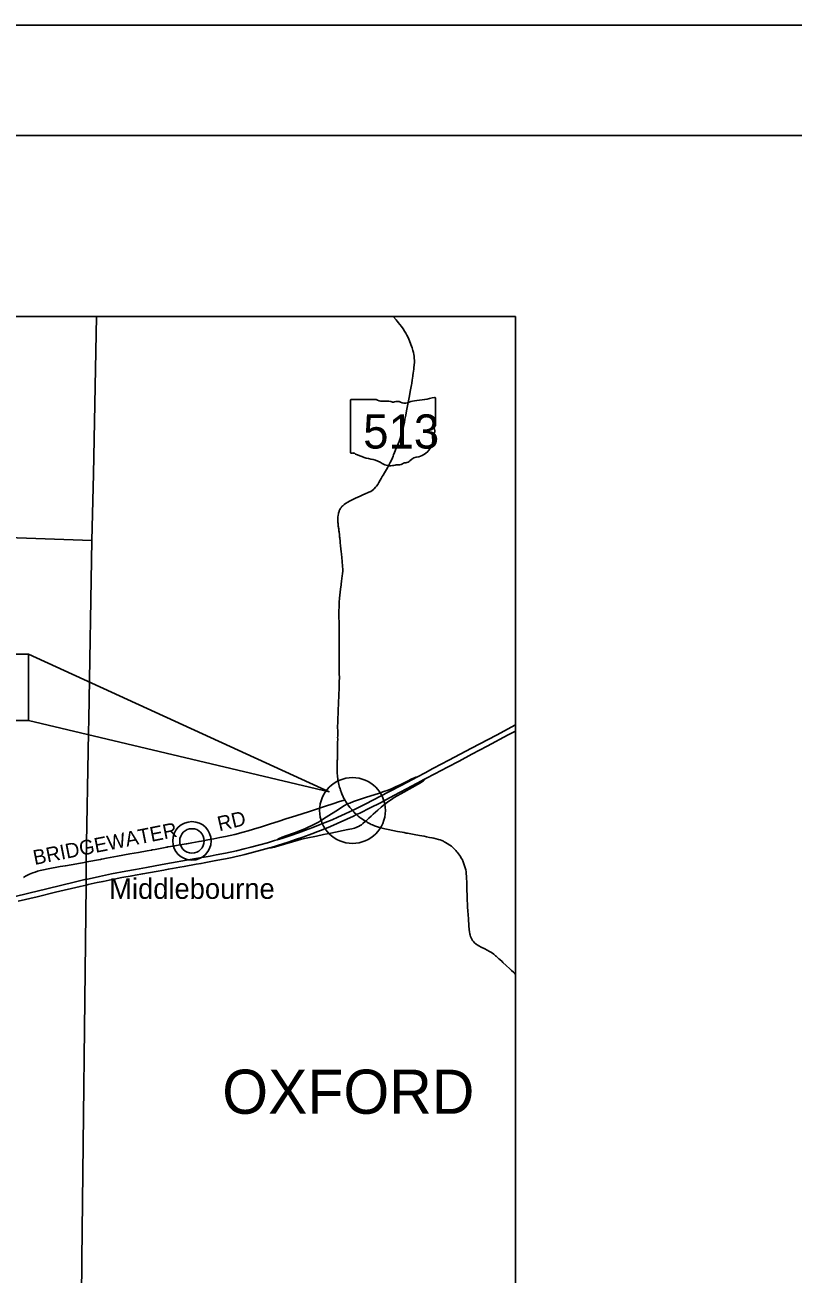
# Model space of a CAD drawing. Extents: x -29.6 to 34, y 0 to 22.
# Drawn here: x 18.65 to 22.13, y 16.34 to 22 of the extents above; entities that cross this region are included whole.
import ezdxf

# ---------------------------------------------------------------- set-up
doc = ezdxf.new("R2010")
doc.units = 0
for name, color, linetype in [('BR_P_Gen_Text', 7, 'Continuous'), ('Default', 7, 'Continuous'), ('GM_X_County_Road', 7, 'Continuous'), ('GM_X_County_Road_Text', 7, 'Continuous'), ('GM_X_Interchange_Ramps', 7, 'Continuous'), ('GM_X_Interstate_Route', 7, 'Continuous'), ('GM_X_State_Route', 7, 'Continuous'), ('GM_X_State_Shield', 7, 'Continuous'), ('GM_X_Township', 7, 'Continuous'), ('GM_X_Township_Text', 7, 'Continuous'), ('GM_X_Unincorporated', 7, 'Continuous'), ('GM_X_Unincorporated_Location', 7, 'Continuous'), ('GM_X_Unincorporated_Text', 7, 'Continuous'), ('GM_X_US_Route', 7, 'Continuous'), ('SH_Border', 7, 'Continuous'), ('SH_Cut_Line', 7, 'Continuous'), ('SH_Text', 7, 'Continuous')]:
    doc.layers.add(name, color=color, linetype=linetype)

msp = doc.modelspace()

# ---------------------------------------------------------------- linework, layer by layer
at = {"layer": 'BR_P_Gen_Text'}
for points in [[(17.1077, 19.1512), (18.6674, 19.1512), (18.6674, 18.8509), (17.1077, 18.8509)], [(18.6674, 19.1512), (18.6674, 18.8509), (20.0294, 18.5277)]]:
    msp.add_lwpolyline(points, close=True, dxfattribs=at)
at = {"layer": 'Default'}
msp.add_circle((20.1356, 18.443), 0.149, dxfattribs=at)
at = {"layer": 'GM_X_County_Road'}
for points in [[(19.4514, 18.305), (19.4797, 18.3101), (19.5073, 18.3153), (19.5343, 18.3205), (19.5606, 18.3257), (19.6029, 18.3352), (19.6396, 18.3445), (19.6628, 18.351), (19.6863, 18.358), (19.7227, 18.3694), (19.7591, 18.3811), (19.8034, 18.3953), (19.833, 18.4048), (19.8789, 18.4195), (19.9408, 18.4388), (19.9636, 18.4462), (20.0131, 18.4625), (20.0459, 18.4728), (20.0762, 18.4834), (20.0929, 18.4888), (20.1004, 18.4912)], [(19.2951, 18.2773), (19.2982, 18.2779), (19.3226, 18.2823), (19.3458, 18.2862), (19.3638, 18.2892), (19.3814, 18.2922), (19.3845, 18.2928)], [(19.3845, 18.2928), (19.3923, 18.2944), (19.4075, 18.2971), (19.4406, 18.3031), (19.4514, 18.305)], [(18.9931, 18.2217), (18.9987, 18.2227), (19.0004, 18.223), (19.0211, 18.2272), (19.0706, 18.2358), (19.1271, 18.2463), (19.1659, 18.2532), (19.2045, 18.2604), (19.2253, 18.2641), (19.2278, 18.2646)], [(19.2278, 18.2646), (19.2411, 18.2669), (19.2868, 18.2756), (19.294, 18.2771), (19.2951, 18.2773)], [(18.644, 18.1398), (18.6541, 18.1457), (18.6632, 18.1504), (18.6719, 18.1543), (18.6867, 18.1605), (18.6969, 18.1644), (18.7074, 18.1677), (18.7208, 18.1713), (18.7357, 18.1748), (18.7557, 18.1789), (18.8102, 18.1888), (18.8345, 18.1933), (18.9286, 18.2099)], [(18.9286, 18.2099), (18.932, 18.2105), (18.9931, 18.2217)]]:
    msp.add_lwpolyline(points, dxfattribs=at)
at = {"layer": 'GM_X_Interchange_Ramps'}
for points in [[(20.4268, 18.594), (20.4226, 18.5934), (20.4191, 18.5924), (20.4123, 18.59), (20.4051, 18.5864), (20.3842, 18.576), (20.351, 18.5594), (20.3312, 18.55), (20.3152, 18.543), (20.2969, 18.5359), (20.277, 18.5288), (20.2528, 18.5206), (20.1988, 18.503), (20.1408, 18.4833), (20.1229, 18.477), (20.1121, 18.4729)], [(20.1948, 18.3944), (20.1971, 18.3964), (20.2101, 18.408), (20.2209, 18.4178), (20.23, 18.4262), (20.2499, 18.4443), (20.2651, 18.4579), (20.2746, 18.4658), (20.286, 18.4749), (20.2965, 18.4828), (20.312, 18.4935), (20.3249, 18.5019), (20.3379, 18.5098), (20.3543, 18.5193), (20.4058, 18.5479), (20.4442, 18.5689), (20.4525, 18.5741), (20.4571, 18.5776), (20.4625, 18.5826), (20.4674, 18.5877)], [(20.1121, 18.4729), (20.1065, 18.47), (20.102, 18.4676), (20.0971, 18.4645), (20.0721, 18.4482), (20.0165, 18.4122), (19.9956, 18.399), (19.9818, 18.3908), (19.9671, 18.3827), (19.9509, 18.3745), (19.935, 18.3671), (19.9196, 18.3605), (19.8993, 18.3525), (19.8726, 18.3427), (19.8337, 18.329), (19.8176, 18.3228), (19.8107, 18.32), (19.8059, 18.3177), (19.8003, 18.3146), (19.7948, 18.3106)], [(19.7624, 18.2746), (19.7681, 18.2748), (19.7752, 18.2757), (19.782, 18.277), (19.8015, 18.2827), (19.8634, 18.302), (19.8844, 18.308), (19.9048, 18.3131), (19.9254, 18.3178), (19.9732, 18.3276), (20.0038, 18.3339), (20.0373, 18.3408), (20.1149, 18.3569), (20.1327, 18.3608), (20.144, 18.3637), (20.1523, 18.3663), (20.1583, 18.3688), (20.1636, 18.3713), (20.1699, 18.3749), (20.1759, 18.3789), (20.1823, 18.3838), (20.1948, 18.3944)]]:
    msp.add_lwpolyline(points, dxfattribs=at)
at = {"layer": 'GM_X_Interstate_Route'}
for points in [[(20.4674, 18.5877), (20.5083, 18.6093), (20.5663, 18.6397), (20.6184, 18.6672), (20.6763, 18.6978), (20.7457, 18.7346), (20.8409, 18.7851), (20.8747, 18.8029)], [(20.4972, 18.6312), (20.5035, 18.6345), (20.5717, 18.6705), (20.6752, 18.7254), (20.7885, 18.785), (20.8747, 18.8305)], [(19.7948, 18.3106), (19.8192, 18.3182), (19.8559, 18.3302), (19.8917, 18.3424), (19.9075, 18.348), (19.9232, 18.3538), (19.9566, 18.3666), (19.9891, 18.3794), (20.0114, 18.3884), (20.043, 18.4016), (20.0697, 18.4132), (20.1023, 18.4278), (20.1228, 18.4371), (20.1356, 18.443), (20.1447, 18.4472), (20.1696, 18.4592), (20.1937, 18.4713), (20.3001, 18.5271), (20.3561, 18.5567), (20.4082, 18.5842), (20.4268, 18.594), (20.4681, 18.6159), (20.4972, 18.6312)], [(20.1512, 18.4229), (20.1543, 18.4244), (20.1692, 18.4316), (20.2154, 18.4546), (20.2621, 18.4784), (20.3033, 18.5001), (20.3514, 18.526), (20.3803, 18.5415), (20.4515, 18.5793)], [(20.4515, 18.5793), (20.4536, 18.5804), (20.4674, 18.5877)], [(19.7624, 18.2746), (19.7957, 18.2845), (19.82, 18.2921), (19.8491, 18.3016), (19.8781, 18.3114), (19.911, 18.323), (19.9514, 18.3377), (19.9779, 18.3478), (20.0029, 18.3577), (20.0359, 18.3713), (20.066, 18.3842), (20.1093, 18.4034), (20.1397, 18.4173), (20.1512, 18.4229)], [(18.6011, 18.0529), (18.669, 18.0694), (18.7497, 18.0887), (18.819, 18.1057), (18.8743, 18.1189), (18.9225, 18.13), (18.9286, 18.1313), (18.9894, 18.1445), (19.0436, 18.1557), (19.1086, 18.1683), (19.1523, 18.1763), (19.2025, 18.1852), (19.2734, 18.1979), (19.4254, 18.2251), (19.4913, 18.237), (19.5178, 18.242), (19.5599, 18.2506), (19.6098, 18.2612), (19.6453, 18.2693), (19.675, 18.2766), (19.7151, 18.2873), (19.7502, 18.2972), (19.7823, 18.3068), (19.7948, 18.3106)], [(18.6211, 18.032), (18.706, 18.0526), (18.7895, 18.0729), (18.9014, 18.0995), (18.929, 18.1057), (18.9384, 18.1078), (18.9512, 18.1106), (18.9789, 18.1166), (19.0053, 18.1221), (19.046, 18.1305), (19.0503, 18.1313), (19.0696, 18.1351), (19.0903, 18.1391), (19.1368, 18.1477), (19.1505, 18.1502), (19.1849, 18.1564), (19.2458, 18.1673), (19.2809, 18.1737), (19.301, 18.1772), (19.3203, 18.1807), (19.3526, 18.1864), (19.3727, 18.1899), (19.4271, 18.1997), (19.4493, 18.2037), (19.463, 18.2061), (19.5167, 18.216), (19.5602, 18.2246), (19.5909, 18.231), (19.6086, 18.235), (19.6299, 18.2399), (19.6476, 18.2441), (19.6864, 18.2539), (19.7258, 18.2643), (19.7595, 18.2737), (19.7624, 18.2746)]]:
    msp.add_lwpolyline(points, dxfattribs=at)
at = {"layer": 'GM_X_State_Route'}
for points in [[(20.0671, 18.6748), (20.0672, 18.6771), (20.0674, 18.6866), (20.0675, 18.6921), (20.0679, 18.708), (20.0681, 18.7175), (20.0681, 18.7276), (20.0684, 18.7497), (20.0685, 18.7674), (20.0684, 18.7743), (20.0685, 18.7804), (20.0685, 18.7858), (20.0685, 18.7895), (20.0685, 18.7972), (20.0685, 18.8012), (20.0685, 18.8064), (20.0683, 18.816), (20.0684, 18.8196), (20.0691, 18.8458), (20.0697, 18.8654), (20.0701, 18.8781), (20.0711, 18.8979), (20.0722, 18.9279), (20.0737, 18.9673), (20.0747, 18.9977), (20.0753, 19.0113), (20.0755, 19.0193), (20.0758, 19.0285), (20.0761, 19.0421), (20.0761, 19.0463), (20.076, 19.0611), (20.0758, 19.0742), (20.0755, 19.1011), (20.0754, 19.1207), (20.0752, 19.1367), (20.0751, 19.16), (20.0751, 19.1797), (20.0751, 19.192), (20.0751, 19.219), (20.0751, 19.2422), (20.0749, 19.2698), (20.0749, 19.2845), (20.0746, 19.2961), (20.0741, 19.3165), (20.0739, 19.3354), (20.074, 19.347), (20.0746, 19.3652), (20.0759, 19.3862), (20.0775, 19.4043), (20.0815, 19.4456), (20.0837, 19.4651), (20.0865, 19.4845), (20.0875, 19.491), (20.088, 19.4945), (20.0894, 19.5046), (20.0908, 19.5161), (20.0914, 19.5263), (20.0915, 19.5357), (20.0906, 19.5477), (20.0881, 19.5728), (20.0867, 19.5873), (20.0851, 19.6049), (20.0842, 19.615), (20.0832, 19.6275), (20.0818, 19.6413), (20.0802, 19.6568), (20.0797, 19.6618), (20.078, 19.6777), (20.0775, 19.682), (20.0764, 19.6907), (20.0747, 19.7043), (20.074, 19.7093), (20.073, 19.718), (20.0722, 19.7237), (20.0719, 19.7266), (20.0714, 19.7308), (20.0708, 19.7357), (20.0701, 19.742), (20.0697, 19.7473), (20.0693, 19.7541), (20.0693, 19.7591), (20.0694, 19.7639), (20.0698, 19.7715), (20.0707, 19.7808), (20.0715, 19.7858), (20.0726, 19.7895), (20.0737, 19.7934), (20.0747, 19.7964), (20.076, 19.7999), (20.0775, 19.8034), (20.0789, 19.8064), (20.081, 19.8101), (20.082, 19.8116), (20.0828, 19.8129), (20.0836, 19.814), (20.0848, 19.8157), (20.0856, 19.8167), (20.0865, 19.8179), (20.0875, 19.8191), (20.0892, 19.8209), (20.0916, 19.8233), (20.0982, 19.8288), (20.1046, 19.8335), (20.1138, 19.8392), (20.1214, 19.8435), (20.1337, 19.8497), (20.15, 19.8576), (20.1705, 19.867), (20.1851, 19.8734), (20.1904, 19.8759), (20.1931, 19.8769), (20.1957, 19.8782), (20.2031, 19.8813), (20.2098, 19.8841), (20.2185, 19.8882), (20.2254, 19.8925), (20.2306, 19.8967), (20.2344, 19.9002), (20.2403, 19.9067), (20.2449, 19.9124), (20.25, 19.9196), (20.255, 19.9277), (20.2611, 19.9385), (20.2653, 19.9462), (20.2706, 19.9557), (20.2742, 19.962), (20.28, 19.972), (20.2891, 19.9868), (20.2955, 19.9974), (20.3007, 20.0069), (20.3071, 20.0193), (20.3132, 20.0325), (20.3193, 20.0473), (20.3221, 20.054), (20.3265, 20.0648), (20.3342, 20.0835), (20.337, 20.0902), (20.3424, 20.103), (20.3467, 20.1138), (20.3512, 20.127), (20.3565, 20.1444), (20.3613, 20.162), (20.3637, 20.1712), (20.3663, 20.1818), (20.3691, 20.1938), (20.3707, 20.2009), (20.3736, 20.2145), (20.3775, 20.2337), (20.381, 20.2523), (20.3871, 20.2837), (20.3899, 20.2987), (20.3924, 20.3131), (20.399, 20.3481), (20.4017, 20.3632), (20.4029, 20.3704), (20.404, 20.3768), (20.4068, 20.394), (20.4076, 20.3998), (20.408, 20.4027), (20.4087, 20.4077), (20.409, 20.4099), (20.4097, 20.4149), (20.4107, 20.4214), (20.4125, 20.4336), (20.4133, 20.4394), (20.4143, 20.4481), (20.4156, 20.4619), (20.4161, 20.4721), (20.4162, 20.4802), (20.4158, 20.4919), (20.4151, 20.4999), (20.414, 20.5086), (20.4122, 20.5173), (20.4097, 20.5264), (20.4056, 20.5389), (20.4004, 20.5533), (20.3939, 20.5696), (20.3873, 20.585), (20.382, 20.5962), (20.377, 20.6052), (20.372, 20.6132), (20.365, 20.6235), (20.3573, 20.6341), (20.3498, 20.6439), (20.3426, 20.6531), (20.3394, 20.6571), (20.3376, 20.6594), (20.3331, 20.665), (20.3219, 20.6792), (20.3214, 20.6798)], [(20.1004, 18.4912), (20.0978, 18.4959), (20.0956, 18.5005), (20.0931, 18.5056), (20.0914, 18.5096), (20.0894, 18.5143), (20.0878, 18.5183), (20.0859, 18.523), (20.0812, 18.5359), (20.0792, 18.5421), (20.0775, 18.5477), (20.0755, 18.5546), (20.0739, 18.5609), (20.0723, 18.568), (20.0709, 18.5751), (20.0695, 18.5822), (20.0687, 18.5886), (20.0678, 18.5958), (20.0672, 18.6031), (20.0667, 18.6088), (20.0666, 18.6114), (20.0665, 18.6165), (20.0664, 18.624), (20.0664, 18.6312), (20.0666, 18.6385), (20.0668, 18.6465), (20.0668, 18.6522), (20.0668, 18.6601), (20.0669, 18.6702), (20.0671, 18.6748)], [(20.1695, 18.4117), (20.162, 18.4177), (20.1555, 18.4234), (20.1543, 18.4244), (20.1517, 18.4268), (20.1438, 18.4343), (20.1412, 18.4369), (20.1356, 18.443), (20.1349, 18.4438), (20.1329, 18.4459), (20.1321, 18.447), (20.128, 18.4521), (20.1239, 18.4571), (20.1208, 18.4611), (20.1191, 18.4634), (20.1164, 18.4668), (20.1131, 18.4715), (20.1121, 18.4729), (20.1097, 18.4762), (20.1065, 18.481), (20.1035, 18.4859), (20.1004, 18.4912)], [(20.1948, 18.3944), (20.19, 18.3972), (20.187, 18.3991), (20.1804, 18.4036), (20.1733, 18.4086), (20.1695, 18.4117)], [(20.6522, 18.1434), (20.652, 18.1466), (20.6514, 18.1545), (20.6503, 18.1648), (20.6488, 18.1746), (20.6466, 18.1835), (20.6453, 18.1884), (20.6425, 18.1975), (20.6393, 18.2065), (20.6357, 18.2152), (20.6349, 18.217), (20.6338, 18.2191), (20.6301, 18.2257), (20.6289, 18.2278), (20.6247, 18.235), (20.6209, 18.241), (20.6165, 18.2474), (20.6115, 18.2534), (20.6091, 18.2563), (20.6038, 18.2626), (20.5971, 18.2693), (20.5841, 18.2809), (20.577, 18.2861), (20.5761, 18.2868), (20.5649, 18.294), (20.5567, 18.2989), (20.5518, 18.3015), (20.5474, 18.3037), (20.5402, 18.307), (20.5329, 18.3097), (20.5251, 18.3121), (20.5156, 18.3148), (20.5048, 18.3173), (20.4956, 18.3194), (20.4841, 18.3216), (20.4711, 18.324), (20.4599, 18.3262), (20.4386, 18.3303), (20.4155, 18.3345), (20.3845, 18.3402), (20.3795, 18.3411), (20.3695, 18.3429), (20.3603, 18.3447), (20.3509, 18.3464), (20.3398, 18.3487), (20.3182, 18.3532), (20.2972, 18.3571), (20.2819, 18.3604), (20.2645, 18.3645), (20.2536, 18.3677), (20.2405, 18.3722), (20.2351, 18.3743), (20.2263, 18.3777), (20.221, 18.3803), (20.216, 18.3828), (20.2104, 18.3857), (20.2042, 18.389), (20.2002, 18.3912), (20.1948, 18.3944)], [(20.8747, 17.7007), (20.8698, 17.706), (20.8651, 17.711), (20.8569, 17.7193), (20.8494, 17.7263), (20.8322, 17.742), (20.8177, 17.7552), (20.814, 17.7587), (20.8032, 17.7685), (20.7994, 17.7719), (20.7924, 17.7782), (20.7864, 17.7835), (20.7843, 17.7854), (20.7813, 17.7879), (20.7756, 17.7931), (20.7649, 17.7999), (20.7563, 17.8053), (20.7456, 17.8109), (20.735, 17.8163), (20.7182, 17.8246), (20.7076, 17.8298), (20.7004, 17.8344), (20.6956, 17.8381), (20.689, 17.8439), (20.6838, 17.8497), (20.6801, 17.8543), (20.6765, 17.8603), (20.6737, 17.8662), (20.6711, 17.8724), (20.6692, 17.8782), (20.6687, 17.8797), (20.6679, 17.8828), (20.6673, 17.8859), (20.6661, 17.8924), (20.6656, 17.8957), (20.6647, 17.9027), (20.6631, 17.9229), (20.6625, 17.9335), (20.662, 17.94), (20.6615, 17.945), (20.6612, 17.9487), (20.6593, 17.9748), (20.6587, 17.9842), (20.6583, 17.9907), (20.6575, 18.0045), (20.6568, 18.0158), (20.6559, 18.0405), (20.6552, 18.06), (20.6545, 18.0825), (20.6543, 18.0879), (20.6539, 18.0958), (20.6537, 18.1048), (20.6535, 18.1138), (20.6532, 18.1238), (20.6528, 18.1329), (20.6527, 18.1365), (20.6522, 18.1434)]]:
    msp.add_lwpolyline(points, dxfattribs=at)
at = {"layer": 'GM_X_State_Shield'}
for p, q in [((20.126, 20.3002), (20.126, 20.0657)), ((20.2429, 20.3043), (20.1298, 20.3043)), ((20.5122, 20.1874), (20.5122, 20.3101)), ((20.5122, 20.1874), (20.5122, 20.1874))]:
    msp.add_line(p, q, dxfattribs=at)
for centre, major_axis, start_param, end_param in [((20.1304, 20.3007), (0.00447, 0), 1.712693, 3.28349), ((20.2698, 20.3315), (0.0434, 0), 4.042523, 4.731795), ((20.2842, 20.1726), (0.1558, 0), 1.404758, 1.657858), ((20.3196, 20.3019), (0.0125, 0), 3.836095, 5.185415), ((20.338, 20.2748), (0.026, 0), 0.950623, 2.079405), ((20.3716, 20.312), (0.0313, 0), 4.081561, 5.145723), ((20.4269, 20.2326), (0.0824, 0), 1.699011, 2.107814), ((20.3746, 20.624), (0.4096, 0), 4.814394, 5.042369), ((20.5079, 20.3106), (0.0043, 0), 6.141152, 7.989035), ((20.5276, 20.1361), (0.0291, 0), 2.387724, 3.262537), ((20.5112, 20.1784), (0.00665, 0), 1.883978, 3.671073), ((20.4689, 20.1629), (0.0399, 0), 5.934695, 6.695948), ((20.5076, 20.1869), (0.0046, 0), 5.05454, 6.418171), ((20.3976, 20.1204), (0.1024, 0), 5.101752, 6.440018), ((20.1305, 20.0652), (0.00451, 0), 3.00124, 4.508301), ((20.1311, 20.0892), (0.0344, 0), 4.665946, 4.897461), ((20.1382, 20.0522), (0.0124, 0), 0.519207, 1.627899), ((20.295, 20.2629), (0.2958, 0), 4.195997, 4.488961), ((20.4408, 19.9999), (0.0561, 0), 1.647645, 2.488434), ((20.2068, 19.9604), (0.0925, 0), 0.823519, 1.323587), ((20.3069, 20.051), (0.0587, 0), 4.026481, 4.996735), ((20.3409, 19.9699), (0.0483, 0), 1.495662, 1.94098), ((20.3451, 20.0335), (0.0313, 0), 4.691044, 5.507374), ((20.3734, 20.0107), (0.00881, 0), 1.147584, 2.315152), ((20.3697, 20.043), (0.0331, 0), 4.937069, 5.64225)]:
    msp.add_ellipse(centre, major_axis=major_axis, ratio=0.8, start_param=start_param, end_param=end_param, dxfattribs=at)
at = {"layer": 'GM_X_Township'}
for points in [[(18.9752, 20.6798), (18.9616, 19.9654), (18.9538, 19.6656), (18.9414, 18.8569), (18.939, 18.7966), (18.9284, 18.2105), (18.9283, 18.1319), (18.9288, 18.1063), (18.9097, 16.4102), (18.8987, 15.1664), (19.0737, 15.1647), (20.0163, 15.1589), (20.3638, 15.157), (20.7287, 15.1536), (20.8747, 15.1526)], [(13.1757, 19.8128), (13.3192, 19.8107), (15.0616, 19.7817), (16.0653, 19.7493), (16.4226, 19.7422), (17.6523, 19.71), (18.6156, 19.678), (18.9538, 19.6656)]]:
    msp.add_lwpolyline(points, dxfattribs=at)
at = {"layer": 'GM_X_Unincorporated'}
for radius in [0.0872, 0.0553]:
    msp.add_circle((19.408, 18.3055), radius, dxfattribs=at)
at = {"layer": 'GM_X_Unincorporated_Location'}
msp.add_line((19.408, 18.3055), (19.408, 18.3055), dxfattribs=at)
at = {"layer": 'GM_X_US_Route'}
for points in [[(20.4674, 18.5877), (20.5083, 18.6093), (20.5663, 18.6397), (20.6184, 18.6672), (20.6763, 18.6978), (20.7457, 18.7346), (20.8409, 18.7851), (20.8747, 18.8029)], [(20.1512, 18.4229), (20.1543, 18.4244), (20.1692, 18.4316), (20.2154, 18.4546), (20.2621, 18.4784), (20.3033, 18.5001), (20.3514, 18.526), (20.3803, 18.5415), (20.4515, 18.5793)], [(20.4515, 18.5793), (20.4536, 18.5804), (20.4674, 18.5877)], [(19.7624, 18.2746), (19.7957, 18.2845), (19.82, 18.2921), (19.8491, 18.3016), (19.8781, 18.3114), (19.911, 18.323), (19.9514, 18.3377), (19.9779, 18.3478), (20.0029, 18.3577), (20.0359, 18.3713), (20.066, 18.3842), (20.1093, 18.4034), (20.1397, 18.4173), (20.1512, 18.4229)], [(18.6211, 18.032), (18.706, 18.0526), (18.7895, 18.0729), (18.9014, 18.0995), (18.929, 18.1057), (18.9384, 18.1078), (18.9512, 18.1106), (18.9789, 18.1166), (19.0053, 18.1221), (19.046, 18.1305), (19.0503, 18.1313), (19.0696, 18.1351), (19.0903, 18.1391), (19.1368, 18.1477), (19.1505, 18.1502), (19.1849, 18.1564), (19.2458, 18.1673), (19.2809, 18.1737), (19.301, 18.1772), (19.3203, 18.1807), (19.3526, 18.1864), (19.3727, 18.1899), (19.4271, 18.1997), (19.4493, 18.2037), (19.463, 18.2061), (19.5167, 18.216), (19.5602, 18.2246), (19.5909, 18.231), (19.6086, 18.235), (19.6299, 18.2399), (19.6476, 18.2441), (19.6864, 18.2539), (19.7258, 18.2643), (19.7595, 18.2737), (19.7624, 18.2746)]]:
    msp.add_lwpolyline(points, dxfattribs=at)
at = {"layer": 'SH_Border'}
msp.add_lwpolyline([(1.5, 21.5), (33.5, 21.5), (33.5, 0.5), (1.5, 0.5)], close=True, dxfattribs=at)
at = {"layer": 'SH_Cut_Line'}
msp.add_lwpolyline([(0, 0), (34, 0), (34, 22), (0, 22)], close=True, dxfattribs=at)
at = {"layer": 'SH_Text'}
for q in [(2.5893, 20.6798), (20.8747, 13.5041)]:
    msp.add_line((20.8747, 20.6798), q, dxfattribs=at)

# ---------------------------------------------------------------- texts
at = {"layer": 'GM_X_County_Road_Text'}
for s, height, rotation, p in [('RD', 0.06658, 13.2138, (19.5321, 18.3488)), ('BRIDGEWATER', 0.066584, 11.2129, (18.6951, 18.1962))]:
    msp.add_text(s, height=height, rotation=rotation, dxfattribs=at).set_placement(p)
at = {"layer": 'GM_X_State_Shield'}
msp.add_text('513', height=0.1545, dxfattribs=at).set_placement((20.184, 20.0822))
at = {"layer": 'GM_X_Township_Text'}
msp.add_text('OXFORD', height=0.19975, rotation=0, dxfattribs=at).set_placement((19.5454, 17.0699))
at = {"layer": 'GM_X_Unincorporated_Text'}
msp.add_text('Middlebourne', height=0.092551, rotation=0, dxfattribs=at).set_placement((19.0333, 18.043))

doc.saveas('drawing.dxf')
